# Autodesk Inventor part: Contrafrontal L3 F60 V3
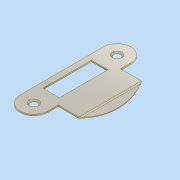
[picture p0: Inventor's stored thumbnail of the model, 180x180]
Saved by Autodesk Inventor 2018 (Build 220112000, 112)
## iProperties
Created: 2020-04
Part Number: Contrafrontal L3 F60 V3
Material: Acero inoxidable
Document SubType Name: Modeling
Designer: PROYECTO
Density: 8 g/cm^3
Appearance: Titanio
Author: PROYECTO
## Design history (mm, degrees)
sketch "Boceto1"
  geometry: L1 (0, 0)-(0, 60); L2 (-10, 60)-(-10, 0); L3 (-6, 47.5)-(-6, 12.5); L4 (-6, 12.5)-(6, 12.5); L5 (6, 12.5)-(6, 47.5); L6 (6, 47.5)-(-6, 47.5); L7 (-6, 47.5)-(6, 12.5); L8 (-6, 12.5)-(6, 47.5); L9 (10, 52.5)-(25, 52.5); L10 (10, 7.5)-(25, 7.5); L11 (25, 52.5)-(25, 7.5); L12 (10, 0)-(10, 7.5); L13 (10, 52.5)-(10, 60); C1 r 2.5 at (0, 60); C2 r 2.5 at (0, 0); A1 r 10 centre (0, 0) between (-10, 0) and (10, 0); A2 r 10 centre (0, 60) between (10, 60) and (-10, 60); 1 further point
  constraints: 28 end point, 6 tangent, 4 centre point, 4 parallel, 4 point on circle, 3 horizontal, 3 midpoint, 2 coincident, 1 perpendicular, 1 vertical
  dimensions: "d1" = 12 distance of L5.end L3.start; "d2" = 35 distance of L4.end L5.end; "d3" = 60 distance of L1.start L1.end; "d4" = 5 diameter of C1; "d5" = 5 diameter of C2; "d7" = 45 distance between parallel lines of L10 L9; "d17" = 7.5 distance from line of L1.start L10; "d18" = 20 distance between parallel lines of L2 L13; "d19" = 35 distance between parallel lines of L2 L11
extrude "Extrusión1" new body sketch "Boceto1" distance "d11" = 1; taper "d12" = 0 deg
chamfer "Chaflán1" distance "d13" = 1; stored, may be unused: second distance "d14" = 2, angle "d15" = 45 deg
sketch "Boceto2"
  geometry: L1 (25, 52.5)-(25, 7.5) reference; A1 r 45 centre (-13.971, 30) between (25, 7.5) and (25, 52.5); 1 further point
  constraints: 2 point on circle, 1 centre point
  dimensions: "d20" = 45 radius of A1
extrude "Extrusión2" join sketch "Boceto2" distance "d21" = 1; taper "d22" = 0 deg
sketch "Boceto4"
  geometry: L1 (-25, 52.5)-(-25, 7.5); A1 r 45 centre (13.971, 30) between (-25, 52.5) and (-25, 7.5) reference; 1 further point
  constraints: 2 end point, 1 vertical
feature "Pieza de plegado1" sketch "Boceto4" dims "d23" = 2, "d24" = 25 deg
node "Sólido1"
other parameters: "d0" = 16
